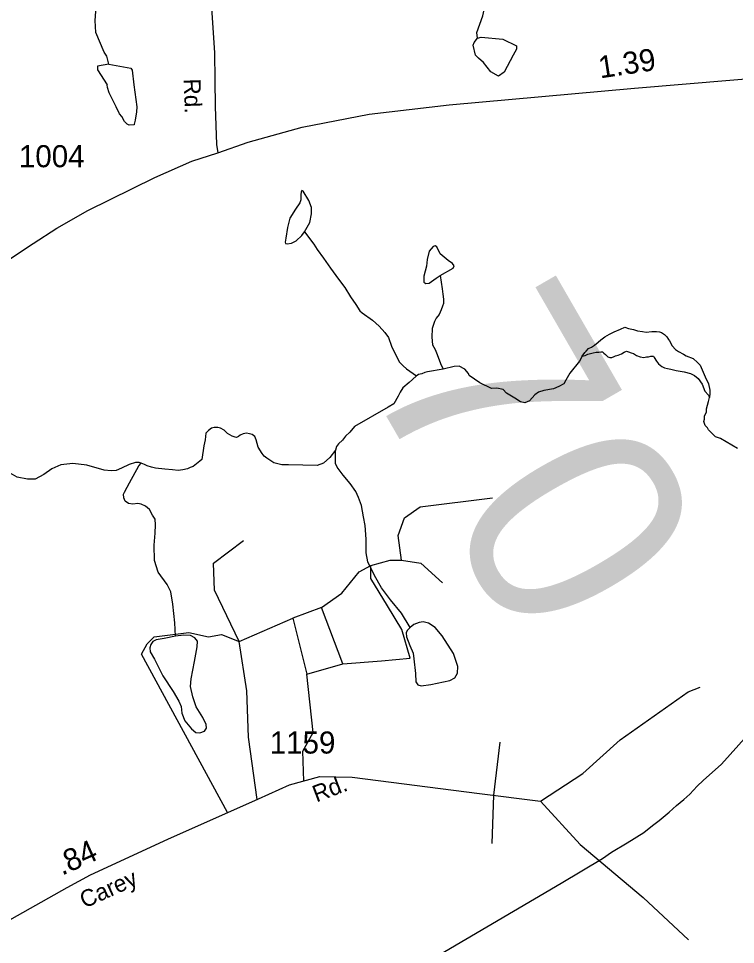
# Model space of a CAD drawing. Extents: x 2056842 to 2160602, y 826753 to 1016856.
# Drawn here: x 2091752 to 2095813, y 905241 to 910482 of the extents above; entities that cross this region are included whole.
import ezdxf

# ---------------------------------------------------------------- set-up
doc = ezdxf.new("R2010")
doc.units = 0
for name, color, linetype in [('Exist Hydrographic Creek Single Shore', 7, 'Continuous'), ('Exist Hydrographic Misc Water Feature', 7, 'Continuous'), ('Exist Railroad Mainline', 7, 'Continuous'), ('Exist Road Non-System Type 51', 7, 'Continuous'), ('Exist Road Secondary Mileage Hundredths English Label', 7, 'Continuous'), ('Exist Road Secondary Structure Standard Bridge Number Label', 7, 'Continuous'), ('Exist Road Secondary Type 51 Attributed', 7, 'Continuous'), ('Exist Road Secondary Type 51 Label', 7, 'Continuous'), ('Exist Road Secondary Type 51 Number Label', 7, 'Continuous')]:
    doc.layers.add(name, color=color, linetype=linetype)

msp = doc.modelspace()

# ---------------------------------------------------------------- linework, layer by layer
at = {"layer": 'Exist Hydrographic Creek Single Shore'}
for points in [[(2094944.8, 908571.6), (2094928.7, 908542.8), (2094875.3, 908475.5), (2094851.9, 908436), (2094840.1, 908413.6), (2094813.4, 908398.6), (2094781.4, 908386.9), (2094728.1, 908377.3), (2094697.1, 908367.7), (2094675.8, 908352.7), (2094645.9, 908318.5), (2094619.2, 908306.8), (2094595.8, 908312.1), (2094562.7, 908333.5), (2094516.8, 908362.3), (2094497.5, 908382), (2094461.3, 908389), (2094431.4, 908387.9), (2094365.3, 908420), (2094304.4, 908461.6), (2094301.3, 908473.4), (2094279.9, 908497.9), (2094247.9, 908513.9), (2094220.1, 908512.9), (2094157.2, 908497.9)], [(2094005.3, 908458.5), (2093964, 908422.1), (2093928.8, 908392.2), (2093913.9, 908366.6), (2093902.2, 908344.2), (2093877.6, 908300.7), (2093846.7, 908282.6), (2093656.2, 908173.7), (2093628.3, 908141.5), (2093604.5, 908117.4), (2093586.7, 908095.4), (2093564.6, 908075.2), (2093552.8, 908059.4), (2093546.8, 908039.1)], [(2095824, 908047.8), (2095728.2, 908105.8), (2095700.1, 908114), (2095684, 908129.7), (2095672.1, 908141.8), (2095660.2, 908153.8), (2095653.9, 908165.8), (2095642, 908177.8), (2095634, 908201.6), (2095637.9, 908213.7), (2095637.9, 908233.7), (2095647.9, 908253.9), (2095649.6, 908273.8), (2095653.6, 908293.8), (2095659.6, 908313.7), (2095665.4, 908337.8)], [(2093546.8, 908039.1), (2093514.7, 907997.1), (2093479, 907965.1), (2093444.4, 907952.5), (2093281.1, 907955.7), (2093243.8, 907955.7), (2093197.9, 907967.5), (2093159, 907994), (2093142.8, 908005.8), (2093132.9, 908019.8), (2093108.8, 908055.8), (2093098.5, 908098), (2093090.6, 908115.9), (2093076.5, 908127.6), (2093060.5, 908131.6), (2093044.5, 908135.5), (2093024.4, 908131.7), (2093008.4, 908123.5), (2092998.4, 908115.5), (2092986.5, 908111.4), (2092978.7, 908111.6), (2092962.4, 908117.5), (2092936.5, 908133.5), (2092916.5, 908151.3), (2092896.4, 908163.2), (2092880.4, 908167.1), (2092860.4, 908167.2), (2092844.5, 908162.9), (2092828.6, 908151.1), (2092812.5, 908135.1), (2092809.5, 908097.7), (2092802, 908063.6), (2092791.3, 907985.6), (2092779.6, 907977.1), (2092741, 907946.9), (2092725.1, 907940.7), (2092709.2, 907932.8), (2092683.2, 907928.4), (2092657.2, 907924.3), (2092625.1, 907928.3), (2092581.2, 907932.2), (2092529.1, 907936.2), (2092505, 907941.9), (2092481.2, 907950), (2092466.9, 907957.8), (2092447.1, 907965.8)], [(2092447.1, 907965.8), (2092435, 907969.6), (2092415, 907969.7), (2092379, 907957.7), (2092335.2, 907937.6), (2092305.1, 907923.4), (2092277.2, 907921.4), (2092237.2, 907925.2), (2092138.6, 907954.3), (2092060.1, 907963), (2091992.7, 907955.5), (2091940.3, 907933.1), (2091895.4, 907900.6), (2091846.7, 907875.6), (2091804.3, 907874.4), (2091744.5, 907886.9), (2091637.2, 907946.8), (2091579.5, 907979.7), (2091507.2, 908002.2), (2091412.4, 907992.2), (2091327.6, 907957.3)]]:
    msp.add_lwpolyline(points, dxfattribs=at)
at = {"layer": 'Exist Hydrographic Misc Water Feature'}
for points in [[(2094351.9, 910371.4), (2094347.8, 910403.3), (2094381.5, 910497.4), (2094407.1, 910611.5), (2094402.8, 910699.5), (2094331.9, 911021.2), (2094337.8, 911061.3), (2094353.6, 911101.3)], [(2092264.7, 910224.8), (2092252.6, 910268.7), (2092238.5, 910292.6), (2092190.1, 910402.5), (2092186, 910470.4), (2092195.4, 910602.6), (2092211.4, 910620.5)], [(2094358.3, 910257.4), (2094340.3, 910275.3), (2094328, 910331.3), (2094332.1, 910347.3), (2094351.9, 910371.4)], [(2094351.9, 910371.4), (2094371.8, 910377.4), (2094495.9, 910365.8), (2094572, 910328), (2094572.2, 910308), (2094554.3, 910274)], [(2094554.3, 910274), (2094502.5, 910177.8), (2094470.7, 910155.8), (2094426.6, 910179.7), (2094386.4, 910233.4), (2094358.3, 910257.4)], [(2092264.7, 910224.8), (2092200.7, 910212.6), (2092200.7, 910192.6), (2092255.1, 910106.8)], [(2092264.7, 910224.8), (2092388.6, 910201.2), (2092396.8, 910189.2), (2092405, 910107.2)], [(2092405, 910107.2), (2092422.4, 909981.7), (2092421, 909953.7), (2092413.4, 909907.8), (2092407.2, 909883.7), (2092407.2, 909879.7), (2092379.3, 909879.6), (2092367.2, 909883.6), (2092353.3, 909899.5), (2092337.1, 909927.4), (2092325.2, 909943.4), (2092304.9, 909983.3), (2092285.4, 910023.1), (2092266, 910060.8), (2092256.7, 910092.7), (2092255.1, 910106.8)], [(2093371.8, 909274.2), (2093401.7, 909327.6), (2093412.4, 909376.7), (2093412.4, 909413), (2093397.4, 909451.5), (2093365.4, 909505.9), (2093357.9, 909509.1), (2093353.7, 909501.7), (2093351.5, 909483.5), (2093351.5, 909456.8), (2093345.1, 909438.7), (2093320.6, 909402.4), (2093289.6, 909352.2), (2093275.8, 909299.9), (2093267.2, 909239), (2093261.9, 909216.6), (2093265.1, 909209.1), (2093273.6, 909207), (2093298.2, 909210.2), (2093324.9, 909224.1), (2093357.9, 909254), (2093371.8, 909274.2)], [(2093371.8, 909274.2), (2093425.3, 909204.9), (2093443.4, 909175), (2093479.4, 909125.1), (2093519.6, 909069.2), (2093563.9, 909007.4), (2093600, 908959.5), (2093632.2, 908907.6), (2093662.4, 908863.6), (2093686.3, 908827.7), (2093698.4, 908815.7), (2093756.5, 908773.9), (2093794.6, 908740.1), (2093826.8, 908704.2), (2093846.9, 908676.3), (2093864.9, 908628.3), (2093889.1, 908576.3), (2093909.2, 908536.5), (2093931.4, 908516.5), (2093949.4, 908498.6), (2094005.6, 908458.8)], [(2094141.2, 909027.4), (2094213.7, 909069), (2094220.1, 909082.9), (2094209.5, 909095.7), (2094186, 909111.7), (2094141.2, 909150.2), (2094122, 909189.7), (2094112.4, 909195), (2094101.7, 909191.8), (2094078.2, 909165.1), (2094066.5, 909118.1), (2094062.2, 909080.8), (2094047.3, 909024.2), (2094047.3, 908990), (2094060.1, 908982.5), (2094078.2, 908984.7), (2094117.7, 909013.5), (2094141.2, 909027.4)], [(2094141.2, 909027.4), (2094152, 908953.1), (2094156.1, 908921.1), (2094160.2, 908893.3), (2094160.2, 908869.3), (2094154.3, 908853.2), (2094146.5, 908833.2), (2094134.4, 908807.1), (2094118.6, 908787), (2094108.5, 908767), (2094094.6, 908727.1), (2094092.8, 908679), (2094096.9, 908635), (2094112.4, 908607.9), (2094124.1, 908581.2), (2094142.2, 908528.9), (2094157.2, 908497.9)], [(2094945, 908571.6), (2094959.1, 908591.7), (2094967.1, 908599.7), (2094980.8, 908613.8), (2094996.8, 908621.8), (2095014.9, 908633.9), (2095034.8, 908650), (2095050.8, 908664), (2095072.7, 908680), (2095098.5, 908696.1), (2095126.6, 908708.2), (2095162.5, 908724.3), (2095186.5, 908734.3), (2095206.6, 908728.4), (2095234.5, 908722.6), (2095258.7, 908714.7), (2095286.6, 908710.7), (2095306.7, 908706.8), (2095338.7, 908710.9), (2095366.5, 908711), (2095382.5, 908709), (2095394.6, 908705), (2095410.6, 908693.1), (2095424.6, 908681.1), (2095432.8, 908665.1), (2095438.7, 908657.1), (2095454.7, 908629.3), (2095473, 908609.3), (2095490.8, 908597.4), (2095519.1, 908581.4), (2095533, 908573.5), (2095573, 908557.6), (2095597.2, 908535.6), (2095613.2, 908519.8), (2095641.3, 908453.8), (2095659.6, 908413.8), (2095667.6, 908378), (2095667.6, 908362), (2095665.7, 908337.9)], [(2094945, 908571.6), (2094961, 908575.7), (2094976.9, 908581.7), (2094991.1, 908585.8), (2095007.1, 908589.9), (2095023.1, 908593.9), (2095039.1, 908593.9), (2095051, 908595.9), (2095059, 908595.9), (2095067, 908588), (2095077, 908580), (2095089.1, 908568.1), (2095101, 908564.1), (2095113.1, 908564.1), (2095125, 908568.2), (2095133, 908572.2), (2095149, 908576.2), (2095167, 908584.3), (2095183, 908594.4), (2095194.9, 908598.4), (2095206.8, 908596.4), (2095223, 908590.5), (2095235.1, 908586.5), (2095252.9, 908574.6), (2095273, 908566.7), (2095292.9, 908562.7), (2095308.9, 908566.8), (2095321, 908566.8), (2095332.9, 908570.8), (2095340.9, 908570.8), (2095349.1, 908570.9), (2095353, 908562.9), (2095365.1, 908543), (2095377.2, 908526.9), (2095395, 908513.1), (2095411.2, 908505.1), (2095427.2, 908501.2), (2095447.3, 908497.2), (2095477.3, 908489.3), (2095521.4, 908481.4), (2095557.2, 908473.5), (2095581.2, 908461.6), (2095601.3, 908443.7), (2095623.5, 908411.8), (2095639.7, 908373.8), (2095659.6, 908349.9), (2095665.7, 908337.9)], [(2094157.2, 908497.9), (2094069.1, 908482.8), (2094053.3, 908478.8), (2094037.4, 908470.6), (2094017.3, 908466.8), (2094005.3, 908458.5)], [(2093970.4, 907034.3), (2093921.7, 907116.6), (2093858.4, 907192.4), (2093808.2, 907259.6), (2093768.8, 907329), (2093730.4, 907406.9), (2093720.7, 907458.2), (2093720.7, 907535.2), (2093715.4, 907613.1), (2093706.9, 907662.2), (2093694.1, 907726.3), (2093678.1, 907771.1), (2093663.6, 907805.8), (2093631.4, 907849.6), (2093591.2, 907897.5), (2093557.2, 907943.5), (2093547.1, 907963.3), (2093547.1, 907995.3), (2093546.9, 908039.4)], [(2092641.9, 906986.9), (2092637.7, 907061.6), (2092627, 907166.3), (2092614.2, 907236.7), (2092595, 907279.4), (2092543.7, 907347.8), (2092522.4, 907414.2), (2092520.3, 907500.9), (2092525.6, 907568.2), (2092527.7, 907616), (2092526.2, 907648.3), (2092512.2, 907670.2), (2092494, 907702.2), (2092471.8, 907722), (2092447.8, 907734), (2092427.9, 907737.9), (2092399.9, 907733.9), (2092375.9, 907737.8), (2092356, 907749.8), (2092349.8, 907769.7), (2092347.8, 907789.7), (2092351.9, 907801.7), (2092367.7, 907829.8), (2092381.6, 907853.8), (2092433.3, 907949.9), (2092447.2, 907966)], [(2093970.4, 907034.3), (2093953.4, 907017.2), (2093948, 907005.5), (2093950.2, 906983.1), (2093968.3, 906933.9), (2093987.5, 906889.1), (2093991.8, 906857.1), (2094000.3, 906774.9), (2094002.5, 906726.8), (2094013.1, 906709.7), (2094032.3, 906704.4), (2094086.8, 906712.9), (2094195.6, 906734.3), (2094223.3, 906749.2), (2094238.3, 906777), (2094240.4, 906814.4), (2094215.9, 906887), (2094151.9, 906987.3), (2094111.3, 907034.3), (2094075, 907058.9), (2094044.1, 907066.3), (2094020.6, 907064.2), (2093990.7, 907051.4), (2093970.4, 907034.3)], [(2092641.9, 906986.9), (2092576.8, 906973.1), (2092532, 906965.7), (2092512.8, 906955), (2092501.1, 906939), (2092496.8, 906920.8), (2092497.9, 906897.3), (2092523.5, 906856.7), (2092569.4, 906760.7), (2092629.1, 906673.1), (2092661.1, 906617.6), (2092672.9, 906587.7), (2092677.1, 906550.3), (2092695.3, 906506.5), (2092731.6, 906461.7), (2092757.2, 906441.4), (2092779.6, 906438.2), (2092805.2, 906448.9), (2092816.9, 906464.9), (2092815.9, 906485.2), (2092796.6, 906525.8), (2092758.2, 906586.6), (2092740.1, 906642.1), (2092727.3, 906700.9), (2092730.5, 906744.6), (2092748.6, 906842.9), (2092763.6, 906926.1), (2092766.8, 906958.2), (2092751.8, 906977.4), (2092726.2, 906989.1), (2092687.8, 906992.3), (2092641.9, 906986.9)]]:
    msp.add_lwpolyline(points, dxfattribs=at)
at = {"layer": 'Exist Railroad Mainline'}
msp.add_lwpolyline([(2093864.2, 905023.2), (2094826.4, 905588.2), (2095059.8, 905727), (2095109.8, 905763.1), (2095199.5, 905815.3), (2095293.3, 905873.7), (2095343.3, 905913.7), (2095381.1, 905941.9), (2095436.9, 905990), (2095478.9, 906028.1), (2095520.8, 906062.3), (2095554.6, 906092.4), (2095596.6, 906136.5), (2095630.4, 906168.6), (2095734.1, 906261.1), (2096029, 906589.8)], dxfattribs=at)
at = {"layer": 'Exist Road Non-System Type 51'}
for p, q in [((2093467.8, 907148.3), (2093306.9, 907088.7)), ((2093589.9, 906829.3), (2093467.8, 907148.3)), ((2093001.5, 906956), (2093306.9, 907088.7)), ((2093306.9, 907088.7), (2093385.8, 906771.2)), ((2093385.8, 906771.2), (2093589.9, 906829.3))]:
    msp.add_line(p, q, dxfattribs=at)
for points in [[(2093920.6, 907416.6), (2093902.7, 907556.7), (2093938.5, 907655.1), (2094027.8, 907717.7), (2094436, 907768.4)], [(2093001.5, 906956), (2092863, 907246.7), (2092857, 907398.7), (2093026.9, 907526.9)], [(2093747.8, 907386.8), (2093858, 907416.6), (2093920.6, 907416.6)], [(2093920.6, 907416.6), (2094030.8, 907398.7), (2094153, 907288.4)], [(2093467.8, 907148.3), (2093584, 907228.8), (2093682.3, 907351), (2093747.8, 907386.8)], [(2093589.9, 906829.3), (2093807.4, 906847.2), (2093971.2, 906862.1), (2093923.6, 907023.1), (2093843.1, 907157.3), (2093747.8, 907312.3), (2093747.8, 907386.8)], [(2092936.5, 905987.1), (2092448.8, 906883.4), (2092481.9, 906942.2), (2092520.4, 906981.4), (2092717.7, 907006.2), (2092828.7, 906981.7), (2092901.7, 906996.3), (2093001.5, 906956)], [(2093104.3, 906061.9), (2093055.2, 906413.5), (2093046.2, 906675.8), (2093001.5, 906956)], [(2093368.3, 906166), (2093362, 906335.9), (2093421.6, 906440.3), (2093385.8, 906771.2)], [(2094707.8, 906052.3), (2094948.4, 906209.2), (2095159.9, 906400), (2095544.2, 906671.3), (2095612.8, 906698.2)], [(2094477.7, 906385.1), (2094442.9, 906085.4), (2094433, 905812.7)], [(2094707.8, 906052.3), (2094933.5, 905806.8), (2095291, 905505.7), (2095547.2, 905267.2)]]:
    msp.add_lwpolyline(points, dxfattribs=at)
at = {"layer": 'Exist Road Secondary Type 51 Attributed'}
for points in [[(2092591.8, 911972), (2092627, 911786), (2092651.5, 911662.7), (2092712.1, 911365.7), (2092784.8, 910964), (2092835.1, 910685.4), (2092863, 910289), (2092864.5, 910133.5), (2092867.1, 909983.9), (2092874.6, 909769.8), (2092880.7, 909721.2)], [(2092880.7, 909721.2), (2093053.9, 909781.6), (2093359.3, 909867.9), (2093737.4, 909940.7), (2094191.9, 909994.6), (2095241.8, 910087.2), (2096074.4, 910158.2), (2096376.2, 910186.9), (2096661.8, 910204.9), (2096918.9, 910225.7)], [(2090692.1, 908210.8), (2090852.8, 908389.2), (2091052.2, 908599.6), (2091324.3, 908841.3), (2091581.2, 909040.9), (2091836.3, 909208.1), (2091969.9, 909296), (2092145.6, 909395.4), (2092523.7, 909581.5), (2092734.5, 909675.5), (2092880.7, 909721.2)], [(2090554.6, 904944.8), (2090615.2, 904939.4), (2090681.3, 904942.7), (2090728.9, 904951.3), (2090787.4, 904968.7), (2091213.9, 905162.4), (2091673.7, 905363.8), (2092027.6, 905563.3), (2092160.6, 905635.2), (2092598.9, 905836.5), (2093110.8, 906064.8), (2093286.9, 906143.9), (2093459.3, 906190.7), (2093642.6, 906187.1), (2094362.9, 906095.4), (2094707.8, 906052.3)]]:
    msp.add_lwpolyline(points, dxfattribs=at)

# ---------------------------------------------------------------- texts
at = {"layer": 'Exist Road Secondary Mileage Hundredths English Label'}
for s, rotation, p in [('1.39', 8.6287, (2095046.5, 910143.1)), ('.84', 24.266, (2091998.5, 905629.1))]:
    msp.add_text(s, height=125, rotation=rotation, dxfattribs=at).set_placement(p)
at = {"layer": 'Exist Road Secondary Structure Standard Bridge Number Label'}
msp.add_text('70', height=1230.31, rotation=300, dxfattribs=at).set_placement((2093688.2, 908485.7))
at = {"layer": 'Exist Road Secondary Type 51 Label'}
for s, rotation, p in [('Rd.', 271.9798, (2092687.8, 910140.7)), ('Rd.', 20.8562, (2093439.6, 906044.3)), ('Carey', 24.266, (2092126.2, 905443.5))]:
    msp.add_text(s, height=95, rotation=rotation, dxfattribs=at).set_placement(p)
at = {"layer": 'Exist Road Secondary Type 51 Number Label'}
for s, p in [('1004', (2091754.7, 909640.5)), ('1159', (2093175.3, 906321.4))]:
    msp.add_text(s, height=125, dxfattribs=at).set_placement(p)

doc.saveas('drawing.dxf')
